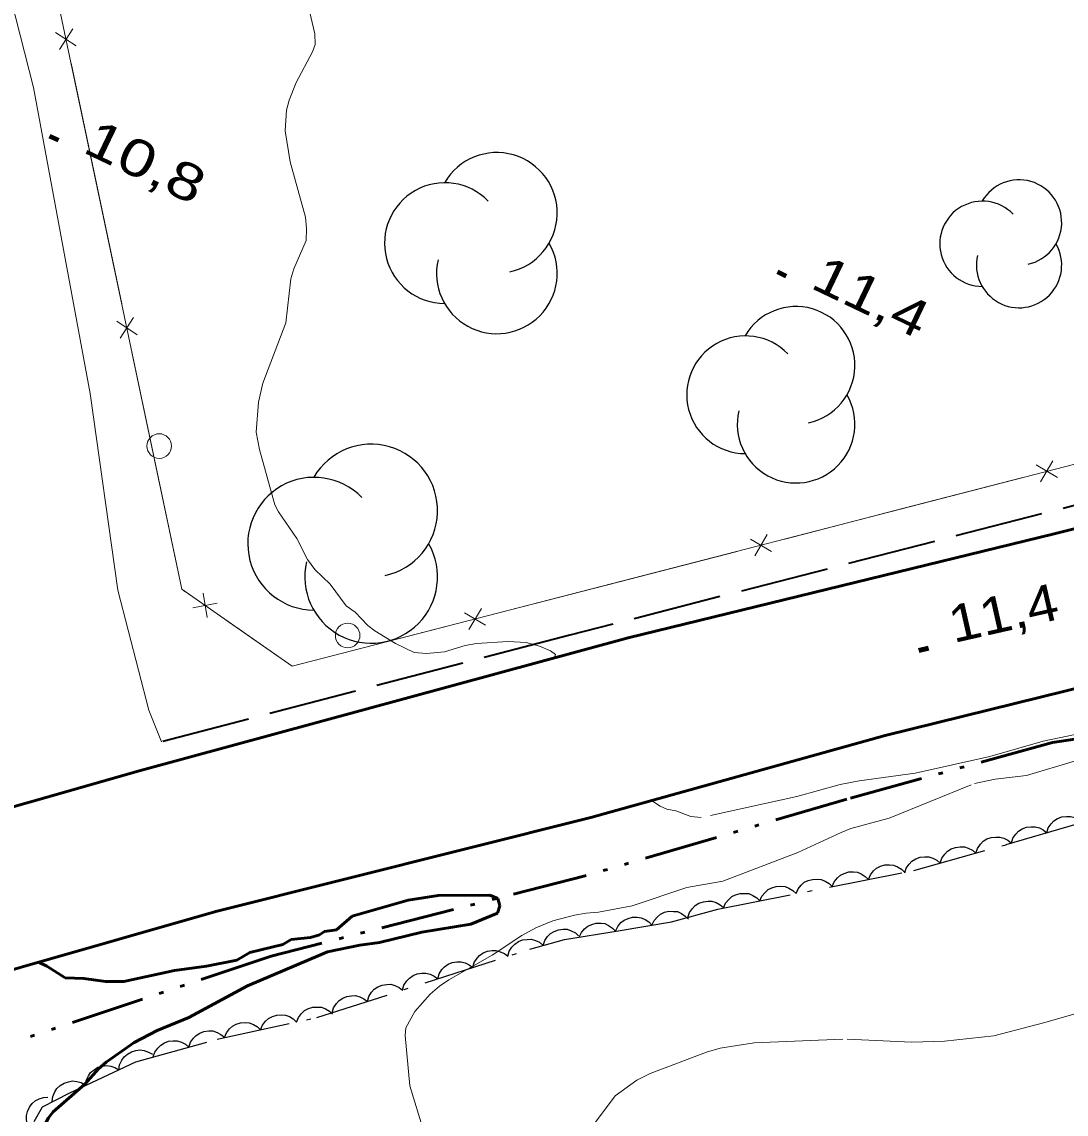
# Model space of a CAD drawing. Extents: x 355726 to 357533, y 5103782 to 5105258.
# Drawn here: x 356041.78 to 356084.23, y 5104766.58 to 5104810.97 of the extents above; entities that cross this region are included whole.
import ezdxf

# ---------------------------------------------------------------- set-up
doc = ezdxf.new("R2010")
doc.units = 0
doc.header["$LTSCALE"] = 0.6
for name, pattern in [('DASH_DOUBLE_DOT', [9.2, 5, -1.2, 0.3, -1.2, 0.3, -1.2]), ('DOT_DASHED', [7.7, 5, -1.2, 0.3, -1.2]), ('LONG_DASHED', [7.5, 6, -1.5])]:
    doc.linetypes.add(name, pattern=pattern)
for name, color, linetype, lineweight in [('1', 7, 'LONG_DASHED', 53), ('19', 7, 'Continuous', 13), ('2', 7, 'LONG_DASHED', 13), ('21', 7, 'LONG_DASHED', 35), ('3', 7, 'Continuous', 140), ('36', 7, 'Continuous', 13), ('37', 7, 'Continuous', 13), ('4', 7, 'DASH_DOUBLE_DOT', 53), ('44', 7, 'Continuous', 25)]:
    doc.layers.add(name, color=color, linetype=linetype, lineweight=lineweight)

msp = doc.modelspace()

# ---------------------------------------------------------------- linework, layer by layer
at = {"layer": '1', "linetype": 'Continuous'}
msp.add_line((356042.79, 5104772.59), (356042.45, 5104772.76), dxfattribs=at)
at = {"layer": '1'}
msp.add_lwpolyline([(356053.92, 5104773.05), (356054.2, 5104773.18), (356055.52, 5104773.45), (356056.32, 5104773.55), (356058.04, 5104773.98), (356060.03, 5104774.3), (356061.11, 5104774.74), (356061.21, 5104775.05), (356061.13, 5104775.34), (356060.8, 5104775.48), (356058.7, 5104775.46), (356057.48, 5104775.28), (356055.2, 5104774.63), (356054.57, 5104774.07), (356054.08, 5104774), (356053.88, 5104773.86), (356053.51, 5104773.76), (356052.73, 5104773.68), (356052.39, 5104773.47), (356051.04, 5104773.15), (356050.52, 5104772.84), (356049.28, 5104772.59), (356047.98, 5104772.41), (356045.92, 5104771.97), (356045.18, 5104771.97), (356044.29, 5104772.09), (356043.53, 5104772.12), (356042.79, 5104772.59)], dxfattribs=at)
at = {"layer": '1', "linetype": 'Continuous'}
msp.add_lwpolyline([(356036.57, 5104755.18), (356036.83, 5104755.26), (356037.3, 5104755.51), (356037.57, 5104755.69), (356038.09, 5104756.15), (356038.59, 5104756.69), (356039.56, 5104757.91), (356040.34, 5104759.04), (356040.69, 5104759.7), (356040.85, 5104760.61), (356040.99, 5104762.34), (356041.21, 5104763.12), (356041.76, 5104764.38), (356042.86, 5104766.43), (356043.05, 5104766.67), (356044.33, 5104767.8), (356044.89, 5104768.42), (356045.2, 5104768.69), (356046.34, 5104769.49), (356047.27, 5104769.98), (356048.57, 5104770.51), (356050.95, 5104771.79), (356053.92, 5104773.05)], dxfattribs=at)
at = {"layer": '19'}
msp.add_lwpolyline([(356047.45, 5104781.71), (356046.94, 5104782.99), (356045.68, 5104787.87), (356044.55, 5104795.86), (356042.25, 5104808.3), (356041.16, 5104812.57), (356038.98, 5104823.11), (356036.63, 5104833.95), (356033.75, 5104846.54), (356031.31, 5104857.57), (356028.87, 5104868.86), (356026.61, 5104869.35)], dxfattribs=at)
at = {"layer": '2', "linetype": 'Continuous'}
msp.add_lwpolyline([(356063.43, 5104785.13), (356063.47, 5104785.26), (356063.26, 5104785.41), (356062.82, 5104785.59), (356062.28, 5104785.74), (356061.54, 5104785.78), (356060.26, 5104785.71), (356059.8, 5104785.62), (356058.96, 5104785.36), (356058.22, 5104785.3), (356057.73, 5104785.34), (356056.97, 5104785.71), (356056.13, 5104786.22), (356055.84, 5104786.43), (356055.32, 5104786.98), (356054.96, 5104787.24), (356054.31, 5104788.12), (356053.68, 5104788.71), (356053.39, 5104789.12), (356052.96, 5104789.97), (356052.21, 5104791.05), (356052.06, 5104791.34), (356051.43, 5104793.59), (356051.3, 5104794.29), (356051.39, 5104795.51), (356051.57, 5104796.28), (356052.5, 5104798.74), (356052.71, 5104800.53), (356052.83, 5104800.93), (356053.34, 5104802.09), (356053.35, 5104802.57), (356053.3, 5104803.03), (356052.68, 5104805.28), (356052.48, 5104806.54), (356052.54, 5104807.38), (356052.64, 5104807.79), (356052.93, 5104808.51), (356053.59, 5104809.75), (356053.7, 5104810.05), (356053.69, 5104810.48), (356053.47, 5104811.41)], dxfattribs=at)
at = {"layer": '2'}
for points in [[(356085.18, 5104782.13), (356083.3, 5104781.73), (356081.13, 5104781.11), (356078.09, 5104780.44), (356075.81, 5104780.13), (356075.04, 5104779.98), (356073.28, 5104779.49), (356069.39, 5104778.63), (356068.97, 5104778.67), (356068.36, 5104778.91), (356068, 5104778.97), (356067.72, 5104779.09), (356067.37, 5104779.33)], [(356065.22, 5104774.78), (356066.58, 5104775.05), (356068.81, 5104775.79), (356070.27, 5104776.05), (356073.32, 5104777.21), (356075.08, 5104778.03), (356075.47, 5104778.18), (356077.03, 5104778.61), (356080.5, 5104780.01), (356081.34, 5104780.19), (356082.62, 5104780.34), (356084.61, 5104780.94)], [(356058.1, 5104765.91), (356057.55, 5104767.73), (356057.36, 5104769.78), (356057.39, 5104770.09), (356057.75, 5104770.75), (356058.38, 5104771.45), (356058.75, 5104771.78), (356059.13, 5104772.04), (356060.9, 5104773.04), (356062.1, 5104773.84), (356062.67, 5104774.15), (356063.36, 5104774.43), (356064.24, 5104774.66), (356064.71, 5104774.75), (356065.22, 5104774.78)], [(356064.85, 5104765.93), (356065.89, 5104767.32), (356066.78, 5104767.96), (356067.32, 5104768.23), (356069.61, 5104769.09), (356070.16, 5104769.26), (356071.55, 5104769.47), (356075.32, 5104769.63), (356077.96, 5104769.5), (356079.28, 5104769.55), (356081.29, 5104769.76), (356083.36, 5104770.3), (356086.87, 5104771.32)]]:
    msp.add_lwpolyline(points, dxfattribs=at)
at = {"layer": '21', "linetype": 'Continuous', "lineweight": 53}
for points in [[(356265.12, 5104834.88), (356257.59, 5104833.43), (356249.24, 5104831.48), (356241.54, 5104829.79), (356235.3, 5104828.24), (356228.28, 5104826), (356220.13, 5104823.86), (356211.31, 5104821.8), (356200.68, 5104819.37), (356190.43, 5104816.84), (356179.84, 5104814.21), (356168.92, 5104811.4), (356156.43, 5104808.45), (356123.02, 5104799.98), (356103.02, 5104795), (356083.74, 5104790.16), (356066.42, 5104785.94), (356046.6, 5104780.55), (356019.42, 5104772.79), (356007.97, 5104769.51), (355987.34, 5104763.62), (355953.78, 5104754.18)], [(356261.8, 5104828.33), (356252.8, 5104826.47), (356245.44, 5104824.76), (356238.22, 5104822.96), (356233.62, 5104821.5), (356227.06, 5104819.47), (356213.46, 5104816), (356201.5, 5104813.08), (356187.44, 5104809.63), (356171.15, 5104805.42), (356156.01, 5104801.55), (356141.11, 5104797.95), (356114.74, 5104791.25), (356102.3, 5104788.23), (356089.5, 5104785.08), (356076.87, 5104781.97), (356064.9, 5104778.63), (356049.66, 5104774.82), (356033.83, 5104770.29), (356032.1, 5104769.8)]]:
    msp.add_lwpolyline(points, dxfattribs=at)
at = {"layer": '21'}
msp.add_lwpolyline([(356160.11, 5104810.43), (356157.25, 5104809.72), (356105.02, 5104796.58), (356064.05, 5104786.04), (356047.45, 5104781.71)], dxfattribs=at)
at = {"layer": '3'}
for p, q in [((356042.9, 5104806.33), (356043.26, 5104806.16)), ((356072.49, 5104800.81), (356072.85, 5104800.64)), ((356078.24, 5104785.42), (356078.63, 5104785.51))]:
    msp.add_line(p, q, dxfattribs=at)
at = {"layer": '36'}
for centre in [(356047.359, 5104793.73), (356055.019, 5104786.03)]:
    msp.add_circle(centre, 0.5, dxfattribs=at)
at = {"layer": '37'}
for p, q in [((356043.3, 5104809.85), (356043.85, 5104810.69)), ((356043.15, 5104810.54), (356043.99, 5104810)), ((356043.78, 5104809.29), (356044.81, 5104804.4)), ((356044.81, 5104804.4), (356045.84, 5104799.51)), ((356045.63, 5104798.8), (356046.46, 5104798.25)), ((356045.77, 5104798.11), (356046.32, 5104798.95)), ((356046.25, 5104797.55), (356047.28, 5104792.66)), ((356083.87, 5104792.45), (356083.01, 5104792.96)), ((356083.19, 5104792.27), (356083.69, 5104793.13)), ((356077.63, 5104791.2), (356082.47, 5104792.45)), ((356072.79, 5104789.95), (356077.63, 5104791.2)), ((356072.25, 5104789.45), (356071.39, 5104789.95)), ((356071.57, 5104789.27), (356072.08, 5104790.13)), ((356066.01, 5104788.2), (356070.85, 5104789.45)), ((356061.17, 5104786.95), (356066.01, 5104788.2)), ((356049.31, 5104786.76), (356049.14, 5104787.75)), ((356048.73, 5104787.16), (356049.72, 5104787.34)), ((356059.95, 5104786.27), (356060.46, 5104787.13)), ((356060.63, 5104786.45), (356059.77, 5104786.95)), ((356054.39, 5104785.2), (356059.23, 5104786.45))]:
    msp.add_line(p, q, dxfattribs=at)
for points in [[(356040.78, 5104914.05), (356040.73, 5104914), (356026.2, 5104918.42), (356023.13, 5104909.33), (356033.59, 5104858.78), (356038.69, 5104834.32), (356042.77, 5104814.09), (356048.28, 5104787.91), (356052.77, 5104784.78), (356091.72, 5104794.84), (356125.59, 5104803.28), (356157.52, 5104811.08), (356157.7, 5104814.25), (356129.85, 5104843.18), (356126.04, 5104847.65), (356126.51, 5104847.98), (356130.53, 5104851.49), (356164.66, 5104815.34)], [(356047.28, 5104792.66), (356048.28, 5104787.91), (356048.4, 5104787.82)], [(356050.04, 5104786.68), (356052.77, 5104784.78), (356054.39, 5104785.2)]]:
    msp.add_lwpolyline(points, dxfattribs=at)
at = {"layer": '4'}
msp.add_lwpolyline([(356093.21, 5104783.23), (356090.04, 5104782.63), (356083.67, 5104781.68), (356075.31, 5104779.38), (356064.67, 5104776.26), (356051.91, 5104773), (356039.32, 5104768.79), (356038.13, 5104768.54)], dxfattribs=at)
at = {"layer": '44', "linetype": 'DOT_DASHED'}
msp.add_lwpolyline([(356042.27, 5104766.28), (356042.61, 5104766.88), (356043.72, 5104767.45), (356046.41, 5104768.7), (356049.71, 5104769.62), (356053.77, 5104770.5), (356062.42, 5104773.28), (356063.83, 5104773.67), (356066.01, 5104774.03), (356068.19, 5104774.39), (356070.07, 5104774.91), (356078.03, 5104776.48), (356081.79, 5104777.53), (356090.24, 5104780), (356093.53, 5104780.92), (356096.35, 5104781.71), (356099.47, 5104782.32), (356104, 5104783.34), (356106.48, 5104783.52), (356108.19, 5104783.75), (356111.15, 5104784.06), (356113.5, 5104784.72), (356115.38, 5104785.24), (356118.03, 5104785.73)], dxfattribs=at)
at = {"layer": '44'}
for points in [[(356083.44, 5104778.01), (356083.5, 5104778.21), (356083.62, 5104778.38), (356083.73, 5104778.5), (356083.88, 5104778.59), (356084.05, 5104778.66), (356084.24, 5104778.68), (356084.41, 5104778.68), (356084.58, 5104778.63), (356084.74, 5104778.55), (356084.88, 5104778.43)], [(356082, 5104777.59), (356082.06, 5104777.79), (356082.18, 5104777.96), (356082.29, 5104778.08), (356082.44, 5104778.17), (356082.61, 5104778.24), (356082.8, 5104778.26), (356082.97, 5104778.26), (356083.14, 5104778.21), (356083.3, 5104778.13), (356083.44, 5104778.01)], [(356080.56, 5104777.19), (356080.62, 5104777.38), (356080.74, 5104777.55), (356080.85, 5104777.67), (356081.01, 5104777.76), (356081.18, 5104777.82), (356081.37, 5104777.84), (356081.53, 5104777.84), (356081.7, 5104777.79), (356081.86, 5104777.71), (356082, 5104777.59)], [(356079.11, 5104776.78), (356079.18, 5104776.98), (356079.3, 5104777.15), (356079.41, 5104777.27), (356079.56, 5104777.36), (356079.73, 5104777.42), (356079.92, 5104777.44), (356080.09, 5104777.44), (356080.25, 5104777.39), (356080.42, 5104777.3), (356080.56, 5104777.19)], [(356077.67, 5104776.38), (356077.73, 5104776.58), (356077.85, 5104776.74), (356077.96, 5104776.86), (356078.12, 5104776.95), (356078.29, 5104777.02), (356078.48, 5104777.04), (356078.64, 5104777.04), (356078.81, 5104776.98), (356078.97, 5104776.9), (356079.11, 5104776.78)], [(356074.72, 5104775.83), (356074.8, 5104776.02), (356074.93, 5104776.18), (356075.05, 5104776.29), (356075.21, 5104776.36), (356075.39, 5104776.42), (356075.58, 5104776.42), (356075.74, 5104776.41), (356075.9, 5104776.34), (356076.06, 5104776.24), (356076.19, 5104776.12)], [(356076.19, 5104776.12), (356076.27, 5104776.31), (356076.4, 5104776.47), (356076.52, 5104776.58), (356076.68, 5104776.65), (356076.86, 5104776.71), (356077.05, 5104776.71), (356077.21, 5104776.7), (356077.37, 5104776.63), (356077.53, 5104776.53), (356077.66, 5104776.41)], [(356073.25, 5104775.54), (356073.33, 5104775.73), (356073.46, 5104775.88), (356073.58, 5104776), (356073.74, 5104776.07), (356073.91, 5104776.12), (356074.11, 5104776.13), (356074.27, 5104776.12), (356074.43, 5104776.05), (356074.59, 5104775.95), (356074.72, 5104775.83)], [(356070.3, 5104774.96), (356070.38, 5104775.15), (356070.51, 5104775.3), (356070.64, 5104775.42), (356070.79, 5104775.49), (356070.97, 5104775.54), (356071.16, 5104775.55), (356071.33, 5104775.54), (356071.49, 5104775.47), (356071.65, 5104775.37), (356071.77, 5104775.25)], [(356071.77, 5104775.25), (356071.86, 5104775.44), (356071.99, 5104775.59), (356072.11, 5104775.71), (356072.27, 5104775.78), (356072.44, 5104775.83), (356072.63, 5104775.84), (356072.8, 5104775.83), (356072.96, 5104775.76), (356073.12, 5104775.66), (356073.25, 5104775.54)], [(356068.85, 5104774.57), (356068.92, 5104774.77), (356069.04, 5104774.94), (356069.15, 5104775.06), (356069.3, 5104775.15), (356069.48, 5104775.21), (356069.67, 5104775.23), (356069.83, 5104775.23), (356070, 5104775.18), (356070.16, 5104775.09), (356070.3, 5104774.97)], [(356067.39, 5104774.26), (356067.48, 5104774.45), (356067.61, 5104774.6), (356067.74, 5104774.71), (356067.9, 5104774.78), (356068.08, 5104774.83), (356068.27, 5104774.82), (356068.43, 5104774.81), (356068.59, 5104774.73), (356068.74, 5104774.63), (356068.87, 5104774.5)], [(356064.43, 5104773.77), (356064.52, 5104773.96), (356064.65, 5104774.11), (356064.78, 5104774.22), (356064.94, 5104774.29), (356065.12, 5104774.34), (356065.31, 5104774.34), (356065.47, 5104774.32), (356065.63, 5104774.25), (356065.78, 5104774.14), (356065.91, 5104774.01)], [(356065.91, 5104774.01), (356066, 5104774.2), (356066.13, 5104774.36), (356066.26, 5104774.46), (356066.42, 5104774.53), (356066.6, 5104774.58), (356066.79, 5104774.58), (356066.95, 5104774.56), (356067.11, 5104774.49), (356067.26, 5104774.39), (356067.39, 5104774.26)], [(356062.97, 5104773.43), (356063.04, 5104773.63), (356063.15, 5104773.8), (356063.27, 5104773.92), (356063.42, 5104774), (356063.59, 5104774.07), (356063.78, 5104774.09), (356063.95, 5104774.09), (356064.11, 5104774.03), (356064.28, 5104773.95), (356064.41, 5104773.83)], [(356061.53, 5104773), (356061.59, 5104773.2), (356061.7, 5104773.37), (356061.81, 5104773.49), (356061.96, 5104773.59), (356062.13, 5104773.66), (356062.32, 5104773.68), (356062.48, 5104773.69), (356062.65, 5104773.64), (356062.82, 5104773.57), (356062.96, 5104773.45)], [(356060.11, 5104772.54), (356060.16, 5104772.74), (356060.28, 5104772.91), (356060.38, 5104773.03), (356060.53, 5104773.13), (356060.7, 5104773.2), (356060.89, 5104773.23), (356061.05, 5104773.23), (356061.22, 5104773.18), (356061.39, 5104773.11), (356061.53, 5104773)], [(356058.68, 5104772.08), (356058.74, 5104772.28), (356058.85, 5104772.45), (356058.96, 5104772.57), (356059.1, 5104772.67), (356059.27, 5104772.74), (356059.46, 5104772.77), (356059.63, 5104772.77), (356059.8, 5104772.73), (356059.96, 5104772.65), (356060.11, 5104772.54)], [(356057.25, 5104771.62), (356057.31, 5104771.82), (356057.42, 5104771.99), (356057.53, 5104772.11), (356057.68, 5104772.21), (356057.85, 5104772.28), (356058.04, 5104772.31), (356058.2, 5104772.31), (356058.37, 5104772.27), (356058.54, 5104772.19), (356058.68, 5104772.08)], [(356055.82, 5104771.16), (356055.88, 5104771.36), (356055.99, 5104771.53), (356056.1, 5104771.66), (356056.25, 5104771.75), (356056.42, 5104771.82), (356056.61, 5104771.85), (356056.77, 5104771.86), (356056.94, 5104771.81), (356057.11, 5104771.73), (356057.25, 5104771.62)], [(356054.39, 5104770.7), (356054.45, 5104770.9), (356054.56, 5104771.07), (356054.67, 5104771.2), (356054.82, 5104771.29), (356054.99, 5104771.36), (356055.18, 5104771.39), (356055.34, 5104771.4), (356055.51, 5104771.35), (356055.68, 5104771.27), (356055.82, 5104771.16)], [(356052.94, 5104770.32), (356053.02, 5104770.51), (356053.15, 5104770.67), (356053.27, 5104770.79), (356053.43, 5104770.87), (356053.6, 5104770.92), (356053.79, 5104770.93), (356053.96, 5104770.92), (356054.12, 5104770.86), (356054.28, 5104770.76), (356054.41, 5104770.64)], [(356050.01, 5104769.69), (356050.09, 5104769.88), (356050.22, 5104770.04), (356050.34, 5104770.15), (356050.49, 5104770.23), (356050.67, 5104770.29), (356050.86, 5104770.3), (356051.02, 5104770.29), (356051.19, 5104770.22), (356051.35, 5104770.13), (356051.48, 5104770)], [(356051.48, 5104770), (356051.56, 5104770.2), (356051.68, 5104770.36), (356051.8, 5104770.47), (356051.96, 5104770.55), (356052.14, 5104770.6), (356052.33, 5104770.61), (356052.49, 5104770.6), (356052.65, 5104770.54), (356052.81, 5104770.45), (356052.94, 5104770.32)], [(356048.56, 5104769.3), (356048.63, 5104769.5), (356048.75, 5104769.66), (356048.86, 5104769.78), (356049.01, 5104769.87), (356049.18, 5104769.94), (356049.38, 5104769.96), (356049.54, 5104769.96), (356049.71, 5104769.9), (356049.87, 5104769.82), (356050.01, 5104769.7)], [(356047.12, 5104768.9), (356047.18, 5104769.1), (356047.3, 5104769.26), (356047.42, 5104769.38), (356047.57, 5104769.47), (356047.74, 5104769.54), (356047.93, 5104769.56), (356048.09, 5104769.56), (356048.26, 5104769.5), (356048.43, 5104769.42), (356048.56, 5104769.3)], [(356045.72, 5104768.38), (356045.75, 5104768.58), (356045.84, 5104768.77), (356045.93, 5104768.9), (356046.07, 5104769.02), (356046.23, 5104769.11), (356046.41, 5104769.16), (356046.57, 5104769.19), (356046.75, 5104769.16), (356046.92, 5104769.1), (356047.08, 5104769.01)], [(356044.36, 5104767.75), (356044.39, 5104767.95), (356044.48, 5104768.13), (356044.57, 5104768.27), (356044.71, 5104768.38), (356044.87, 5104768.48), (356045.05, 5104768.53), (356045.21, 5104768.55), (356045.39, 5104768.53), (356045.56, 5104768.47), (356045.72, 5104768.38)], [(356043.01, 5104767.09), (356043.03, 5104767.29), (356043.12, 5104767.48), (356043.2, 5104767.62), (356043.33, 5104767.74), (356043.49, 5104767.84), (356043.67, 5104767.89), (356043.83, 5104767.93), (356044.01, 5104767.91), (356044.19, 5104767.86), (356044.34, 5104767.77)], [(356042.09, 5104765.97), (356042, 5104766.15), (356041.97, 5104766.35), (356041.96, 5104766.52), (356042.01, 5104766.69), (356042.08, 5104766.86), (356042.2, 5104767.01), (356042.32, 5104767.12), (356042.48, 5104767.2), (356042.65, 5104767.26), (356042.83, 5104767.27)]]:
    msp.add_lwpolyline(points, dxfattribs=at)
for centre, radius, start, end in [((356061.085, 5104803.203), 2.454, 282.2692, 149.7263), ((356058.974, 5104801.976), 2.454, 44.1154, 269.804), ((356082.314, 5104802.816), 1.733, 282.2692, 149.7263), ((356080.824, 5104801.949), 1.733, 44.1154, 269.804), ((356061.085, 5104800.749), 2.454, 166.9369, 29.6212), ((356082.314, 5104801.083), 1.733, 166.9369, 29.6212), ((356073.248, 5104797.01), 2.391, 282.2692, 149.7263), ((356071.193, 5104795.814), 2.391, 44.1154, 269.804), ((356073.248, 5104794.619), 2.391, 166.9369, 29.6212), ((356055.977, 5104791.11), 2.697, 282.2692, 149.7263), ((356053.657, 5104789.761), 2.697, 44.1154, 269.804), ((356055.977, 5104788.413), 2.697, 166.9369, 29.6212)]:
    msp.add_arc(centre, radius, start, end, dxfattribs=at)

# ---------------------------------------------------------------- texts
at = {"layer": '3'}
for s, rotation, width, p in [('10,8   ', 334.423, 1.3, (356044.19, 5104805.7)), ('11,4   ', 334.423, 1.25, (356073.78, 5104800.18)), ('11,4   ', 12.743, 1.15, (356079.65, 5104785.72))]:
    msp.add_text(s, height=1.5, rotation=rotation, dxfattribs=dict(at, width=width)).set_placement(p)

doc.saveas('drawing.dxf')
